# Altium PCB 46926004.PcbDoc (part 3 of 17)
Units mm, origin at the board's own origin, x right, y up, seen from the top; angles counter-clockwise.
Board outline 250 x 200 mm, 6 copper layers (Top Layer, INT1_GND, INT2_SIG, INT3_SIG, INT4_GND, Bottom Layer), stack 1.71 mm thick; 1450 components, 1293 nets, 5656 pads, 2307 vias.
Unrouted connection lines stored in the file: 2.
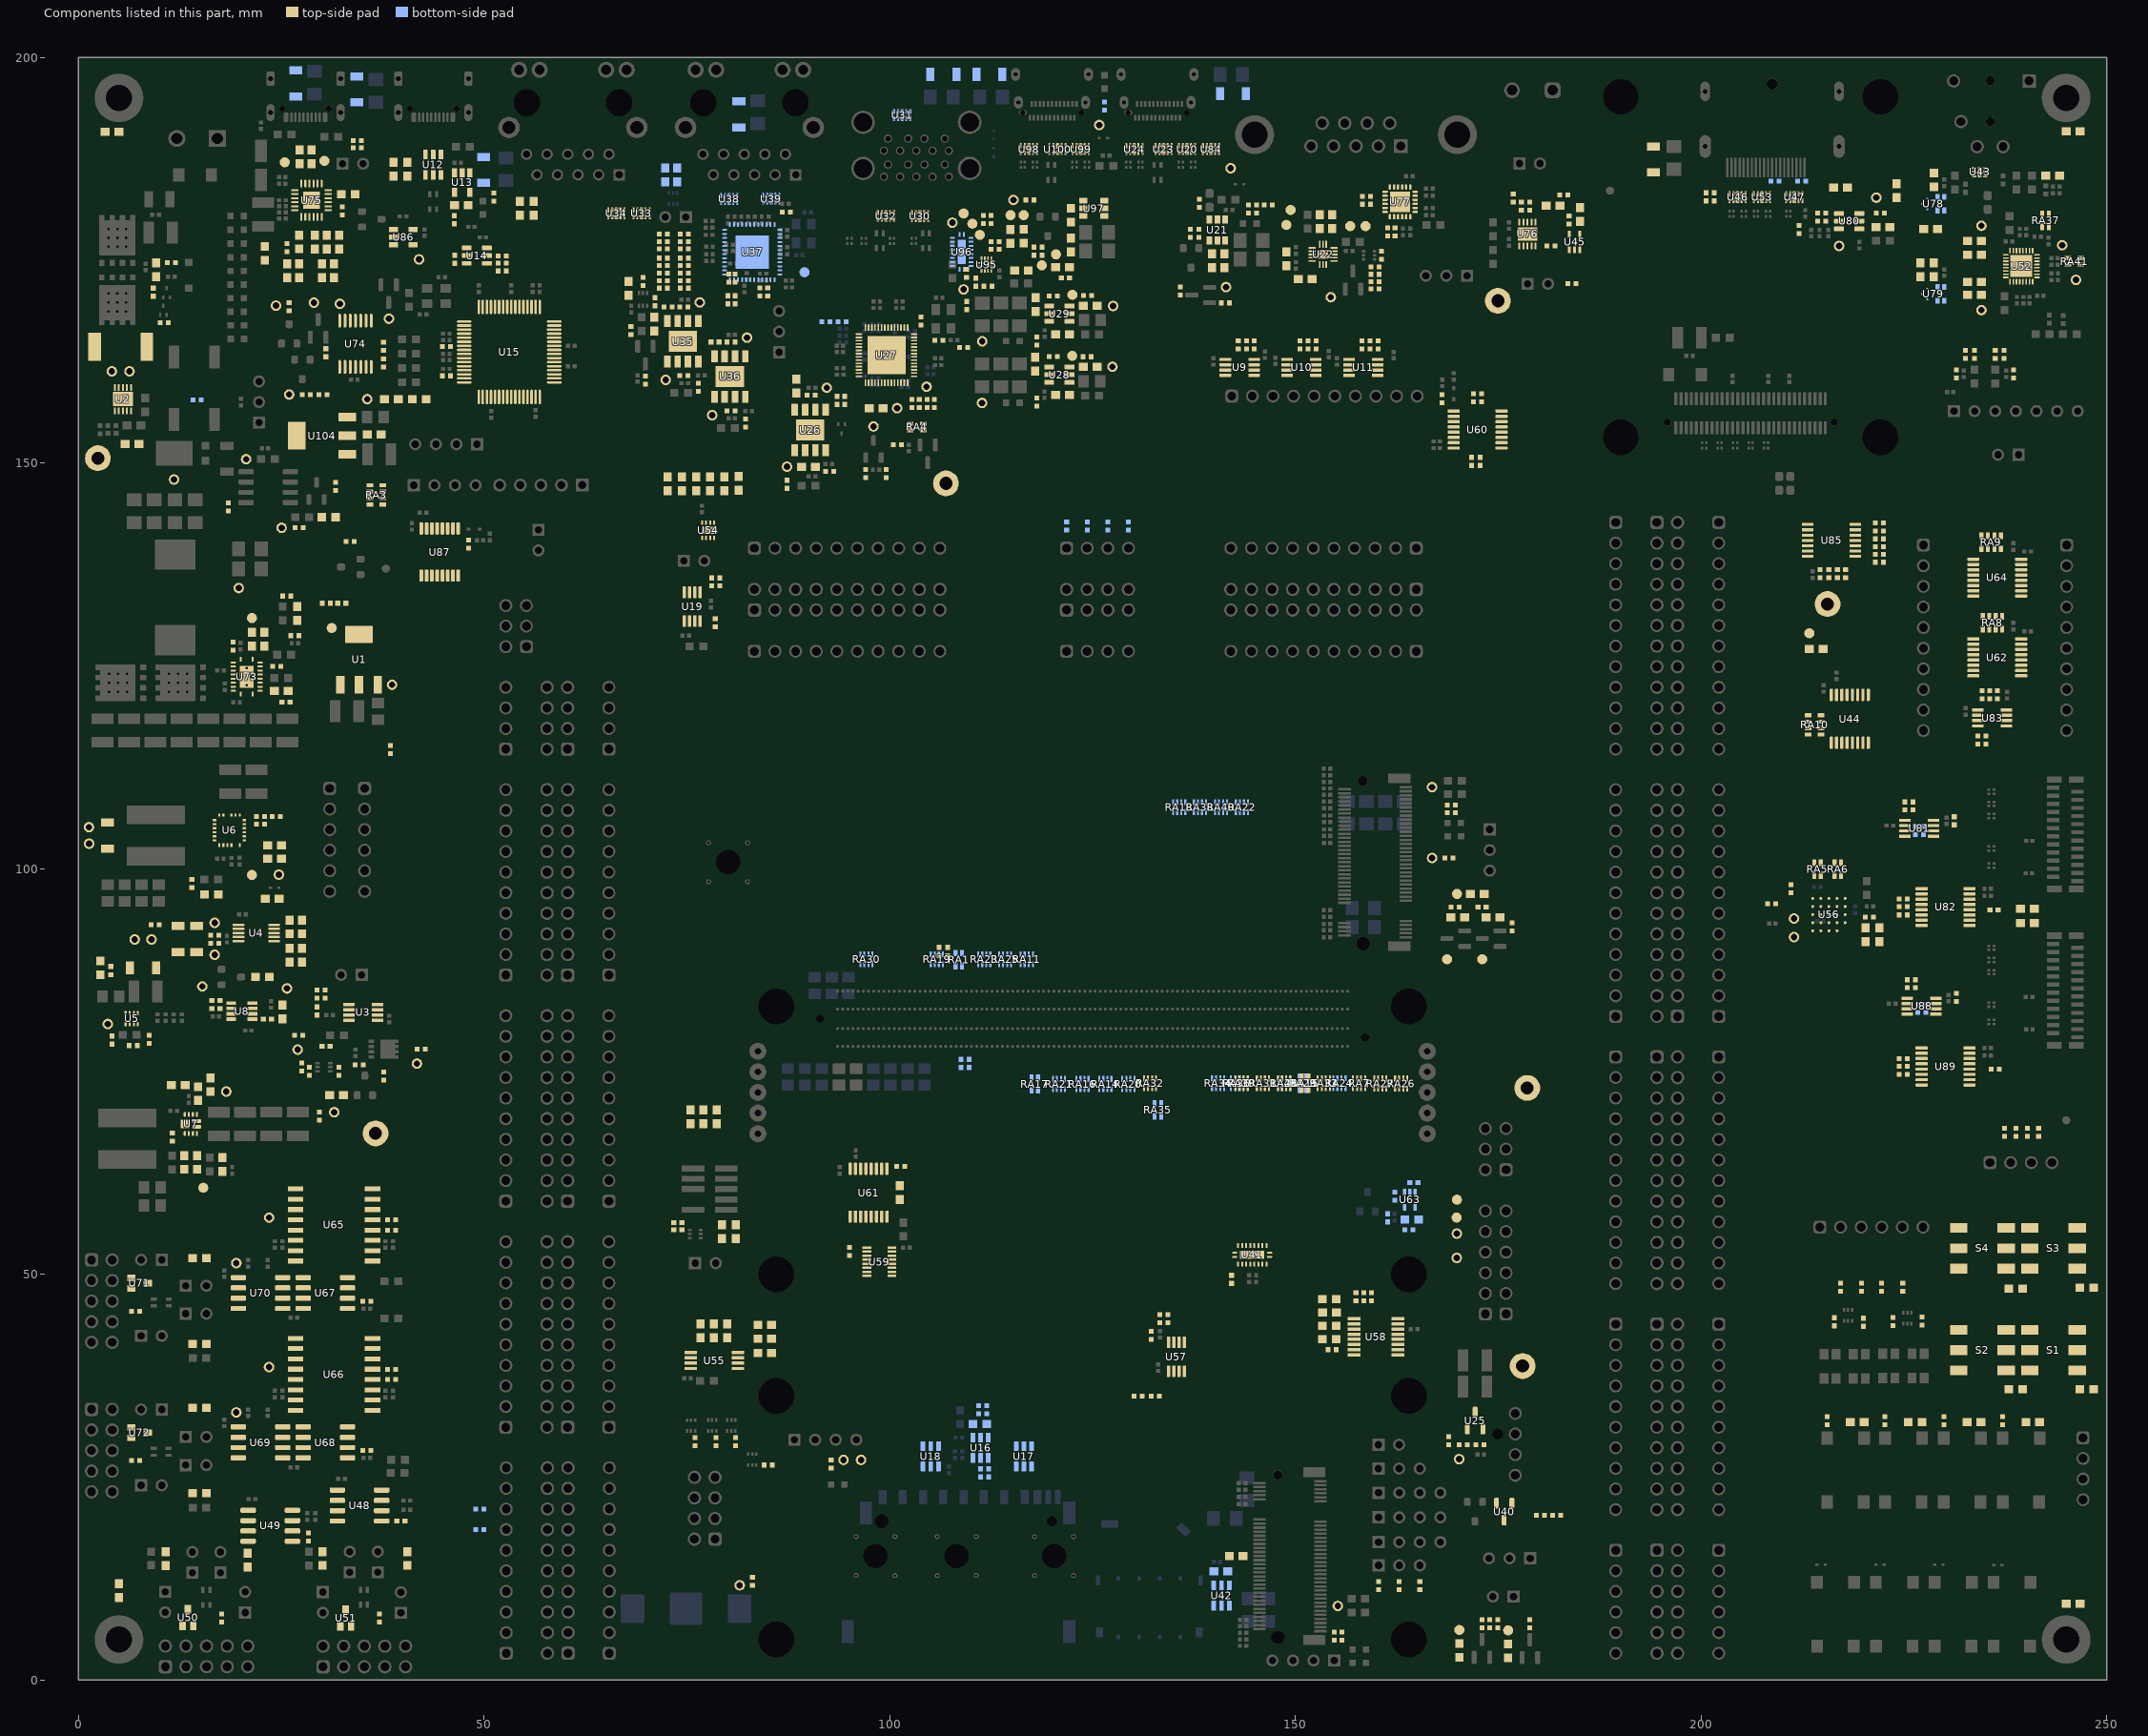
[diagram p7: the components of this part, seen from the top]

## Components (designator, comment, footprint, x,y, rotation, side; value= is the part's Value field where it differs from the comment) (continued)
R6 "1144-Res-0603-24.9K" R/0603 6.623,152.364 r180 top value=24.9K
R7 "1216-Res-0603-20K" R/0603 9.55,173.82 r90 top value=20K
R8 "2225-Res-2512-0.003ohm-2W" R/2512 5.223,164.347 r180 top value=0.003/2W
R9 "1977-Res-0402-100K" R0402_RESC1005L 9.225,171.065 r90 top value=100K
R10 "1572-Res-0402-10K" R0402_RESC1005L 14.645,157.775 r0 bottom value=10K
R11 "0195-Res-0603-0.0ohm" R/0603 245.85,9.425 r0 top value=0.0
R12 "1540-Res-0402-200k" R0402_RESC1005L 29.413,82.465 r270 top value=200K
R13 "2233-Res-0402-4.7K" R0402_RESC1005L 29.925,85.025 r0 top value=4.7K
R14 "2233-Res-0402-4.7K" R0402_RESC1005L 29.925,84.025 r0 top value=4.7K
R15 "0195-Res-0603-0.0ohm" R/0603 27.55,89.325 r90 top value=0.0
R16 "0000-Res-0603-DNP" R/0603 26.05,92.825 r270 top value=DNP
R17 "0195-Res-0603-0.0ohm" R/0603 27.55,92.825 r270 top value=0.0
R18 "0000-Res-0603-DNP" R/0603 26.042,89.325 r90 top value=DNP
R19 "1538-Res-0402-27k" R0402_RESC1005L 37.65,74.42 r90 top value=27K
R20 "1538-Res-0402-27k" R0402_RESC1005L 34.625,75.8 r180 top value=27K
R21 "0257-Res-0402-10ohm" R0402_RESC1005L 16.8,90.825 r180 top value=10
R22 "0034-Res-1206-0.010" R/1206 14.55,91.325 r90 top value=0.010/1W
R23 "0034-Res-1206-0.010" R/1206 12.3,91.325 r90 top value=0.010/1W
R24 "2233-Res-0402-4.7K" R0402_RESC1005L 42.225,77.775 r180 top value=4.7K
R25 "0257-Res-0402-10ohm" R0402_RESC1005L 16.8,91.825 r180 top value=10
R26 "2233-Res-0402-4.7K" R0402_RESC1005L 9.465,93.075 r0 top value=4.7K
R27 "1572-Res-0402-10K" R0402_RESC1005L 4,87.45 r90 top value=10K
R28 "0195-Res-0603-0.0ohm" R/0603 31.8,72.075 r0 top value=0.0
R29 "1538-Res-0402-27k" R0402_RESC1005L 8.725,78.95 r90 top value=27K
R30 "1538-Res-0402-27k" R0402_RESC1005L 6.748,78.2 r0 top value=27K
R31 "1538-Res-0402-27k" R0402_RESC1005L 4.128,78.875 r90 top value=27K
R32 "0195-Res-0603-0.0ohm" R/0603 24.191,102.907 r180 top value=0.0
R33 "0195-Res-0603-0.0ohm" R/0603 16.3,73.375 r270 top value=0.0
R34 "0000-Res-0603-DNP" R/0603 24.195,101.232 r180 top value=DNP
R35 "1977-Res-0402-100K" R0402_RESC1005L 24.4,106.45 r0 top value=100K
R36 "1538-Res-0402-27k" R0402_RESC1005L 22.45,106.45 r0 top value=27K
R37 "1977-Res-0402-100K" R0402_RESC1005L 11.575,66.9 r90 top value=100K
R38 "0195-Res-0603-0.0ohm" R/0603 2.725,87.775 r90 top value=0.0
R39 "0034-Res-1206-0.010" R/1206 7.975,87.775 r180 top value=0.010/1W
R40 "2233-Res-0402-4.7K" R0402_RESC1005L 38.444,114.675 r270 top value=4.7K
R41 "0866-Res-0603-220K" R/0603 14.775,72.275 r90 top value=220K
R42 "0866-Res-0603-220K" R/0603 12.325,73.35 r180 top value=220K
R43 "1572-Res-0402-10K" R0402_RESC1005L 28.351,17.633 r270 top value=10K
R44 "1144-Res-0603-24.9K" R/0603 17.725,63.525 r90 top value=24.9K
R45 "1538-Res-0402-27k" R0402_RESC1005L 13.991,98.175 r90 top value=27K
R46 "1216-Res-0603-20K" R/0603 16.391,96.825 r180 top value=20K
R47 "1550-Res-0402-15K" R0402_RESC1005L 22.45,105.5 r180 top value=15K
R48 "0866-Res-0603-220K" R/0603 14.627,63.8 r90 top value=220K
R49 "1144-Res-0603-24.9K" R/0603 13.052,63.8 r90 top value=24.9K
R50 "1572-Res-0402-10K" R0402_RESC1005L 39.75,19.6 r180 top value=10K
R51 "0034-Res-1206-0.010" R/1206 3.582,104.075 r90 top value=0.010/1W
R52 "1536-Res-0402-1.87K" R0402_RESC1005L 33.504,140.34 r0 top value=1.87K
R53 "1977-Res-0402-100K" R0402_RESC1005L 27.55,75.55 r270 top value=100K
R54 "0195-Res-0603-0.0ohm" R/0603 25.175,82.35 r90 top value=0.0
R55 "1538-Res-0402-27k" R0402_RESC1005L 23.3,81.475 r180 top value=27K
R56 "1977-Res-0402-100K" R0402_RESC1005L 32.125,75.05 r270 top value=100K
R57 "1977-Res-0402-100K" R0402_RESC1005L 28.472,75.05 r270 top value=100K
R58 "1572-Res-0402-10K" R0402_RESC1005L 16.95,82.775 r180 top value=10K
R59 "1572-Res-0402-10K" R0402_RESC1005L 16.95,83.775 r0 top value=10K
R60 "2233-Res-0402-4.7K" R0402_RESC1005L 30.525,78.125 r180 top value=4.7K
R61 "0176-Res-0603-300K" R/0603 70.95,167.11 r90 top value=300K
R62 "0000-Res-0402-DNP" R0402_RESC1005L 72.095,172.487 r180 top value=DNP
R63 "1977-Res-0402-100K" R0402_RESC1005L 71.051,169.889 r270 top value=100K
R64 "0195-Res-0603-0.0ohm" R/0603 22.675,86.65 r0 top value=0.0
R65 "0000-Res-0402-DNP" R0402_RESC1005L 94.122,167.443 r180 bottom value=DNP
R66 "0000-Res-0402-DNP" R0402_RESC1005L 108.8,76 r90 bottom value=DNP
R67 "1572-Res-0402-10K" R0402_RESC1005L 35.55,46.7 r0 top value=10K
R68 "1572-Res-0402-10K" R0402_RESC1005L 35.55,28.275 r0 top value=10K
R69 "1540-Res-0402-200k" R0402_RESC1005L 144.94,164.559 r270 top value=200K
R70 "1540-Res-0402-200k" R0402_RESC1005L 152.56,164.559 r270 top value=200K
R71 "2233-Res-0402-4.7K" R0402_RESC1005L 142.95,164.559 r270 top value=4.7K
R72 "2233-Res-0402-4.7K" R0402_RESC1005L 150.57,164.559 r270 top value=4.7K
R73 "2233-Res-0402-4.7K" R0402_RESC1005L 143.955,164.559 r270 top value=4.7K
R74 "2233-Res-0402-4.7K" R0402_RESC1005L 151.575,164.559 r270 top value=4.7K
R75 "1536-Res-0402-1.87K" R0402_RESC1005L 49.455,18.54 r0 bottom value=1.87K
R76 "1536-Res-0402-1.87K" R0402_RESC1005L 49.455,21.08 r0 bottom value=1.87K
R77 "1540-Res-0402-200k" R0402_RESC1005L 160.18,164.559 r270 top value=200K
R78 "2233-Res-0402-4.7K" R0402_RESC1005L 158.19,164.559 r270 top value=4.7K
R79 "2233-Res-0402-4.7K" R0402_RESC1005L 159.195,164.559 r270 top value=4.7K
R80 "0227-Res-0603-5.1K" R/0603 38.813,186.22 r270 top value=5.1K
R81 "0227-Res-0603-5.1K" R/0603 40.55,186.225 r270 top value=5.1K
R82 "1860-Res-1206-1M-5%-0.25W" R/1206 34.3,196.06 r90 bottom value=1M/0.25W
R83 "2233-Res-0402-4.7K" R0402_RESC1005L 51.2,182.783 r90 top value=4.7K
R84 "0176-Res-0603-300K" R/0603 47.187,181.783 r180 top value=300K
R85 "1539-Res-0402-86.6k" R0402_RESC1005L 46.341,179.994 r90 top value=86.6K
R86 "1538-Res-0402-27k" R0402_RESC1005L 52.24,175.55 r180 top value=27K
R87 "1538-Res-0402-27k" R0402_RESC1005L 52.24,174.625 r180 top value=27K
R88 "1536-Res-0402-1.87K" R0402_RESC1005L 46.39,175.112 r90 top value=1.87K
R89 "1538-Res-0402-27k" R0402_RESC1005L 52.24,173.675 r180 top value=27K
R90 "1538-Res-0402-27k" R0402_RESC1005L 45.34,160.75 r0 top value=27K
R91 "1537-Res-0402-12K" R0402_RESC1005L 45.34,164.35 r0 top value=12K
R92 "1542-Res-0402-1M" R0402_RESC1005L 80.975,29.384 r90 top value=1M
R93 "1542-Res-0402-1M" R0402_RESC1005L 76.009,29.365 r90 top value=1M
R94 "1542-Res-0402-1M" R0402_RESC1005L 78.595,29.384 r90 top value=1M
R95 "1572-Res-0402-10K" R0402_RESC1005L 48.1,140 r270 top value=10K
R96 "0000-Res-0603-DNP" R/0603 111.1,31.58 r0 bottom value=DNP
R97 "1539-Res-0402-86.6k" R0402_RESC1005L 111.694,26.035 r180 bottom value=86.6K
R98 "1539-Res-0402-86.6k" R0402_RESC1005L 111.694,25.035 r180 bottom value=86.6K
R99 "1536-Res-0402-1.87K" R0402_RESC1005L 92.775,26.631 r90 top value=1.87K
R100 "1540-Res-0402-200k" R0402_RESC1005L 78.501,130.298 r90 top value=200K
R101 "1758-Res-0603-2K" R/0603 141.27,174.936 r270 top value=2K
R102 "2233-Res-0402-4.7K" R0402_RESC1005L 78.575,134.885 r180 top value=4.7K
R103 "2233-Res-0402-4.7K" R0402_RESC1005L 78.575,135.835 r180 top value=4.7K
R104 "1538-Res-0402-27k" R0402_RESC1005L 141.37,169.742 r0 top value=27K
R105 "1552-Res-0402-120" R0402_RESC1005L 135.815,171.203 r90 top value=120
R106 "0000-Res-0603-DNP" R/0603 148.871,175.165 r270 top value=DNP
R107 "0000-Res-0603-DNP" R/0603 151.196,172.665 r0 top value=DNP
R108 "1572-Res-0402-10K" R0402_RESC1005L 138.145,182.036 r270 top value=10K
R109 "0000-Res-0603-DNP" R/0603 154.546,179.74 r90 top value=DNP
R110 "0195-Res-0603-0.0ohm" R/0603 152.996,179.74 r90 top value=0.0
R111 "1552-Res-0402-120" R0402_RESC1005L 159.796,174.165 r0 top value=120
R112 "1758-Res-0603-2K" R/0603 139.712,174.936 r270 top value=2K
R113 "1572-Res-0402-10K" R0402_RESC1005L 160.596,175.615 r90 top value=10K
R114 "1538-Res-0402-27k" R0402_RESC1005L 146.64,181.81 r180 top value=27K
R115 "1977-Res-0402-100K" R0402_RESC1005L 201.6,182.817 r270 top value=100K
R116 "1572-Res-0402-10K" R0402_RESC1005L 159.796,173.265 r180 top value=10K
R117 "1572-Res-0402-10K" R0402_RESC1005L 159.796,172.365 r180 top value=10K
R118 "1572-Res-0402-10K" R0402_RESC1005L 159.796,171.465 r180 top value=10K
R119 "2233-Res-0402-4.7K" R0402_RESC1005L 144.695,180.8 r180 top value=4.7K
R120 "1860-Res-1206-1M-5%-0.25W" R/1206 142.3,195.55 r0 bottom value=1M/0.25W
R121 "1552-Res-0402-120" R0402_RESC1005L 69.576,172.39 r90 top value=120
R122 "1572-Res-0402-10K" R0402_RESC1005L 100.945,152.249 r0 top value=10K
R123 "1552-Res-0402-120" R0402_RESC1005L 92.585,148.95 r0 top value=120
R124 "0000-Res-0603-DNP" R/0603 89.976,149.549 r180 top value=DNP
R125 "0000-Res-0402-DNP" R0402_RESC1005L 102.737,157.337 r270 top value=DNP
R126 "1540-Res-0402-200k" R0402_RESC1005L 103.646,157.337 r90 top value=200K
R127 "1540-Res-0402-200k" R0402_RESC1005L 105.495,157.337 r90 top value=200K
R128 "0000-Res-0402-DNP" R0402_RESC1005L 104.596,157.337 r270 top value=DNP
R129 "1538-Res-0402-27k" R0402_RESC1005L 90.326,158.381 r0 top value=27K
R130 "0342-Res-0603-56K" R/0603 88.481,159.504 r90 top value=56K
R131 "0195-Res-0603-0.0ohm" R/0603 98.316,156.764 r0 top value=0.0
R132 "1537-Res-0402-12K" R0402_RESC1005L 103.872,167.496 r270 top value=12K
R133 "1650-Res-0402-1K" R0402_RESC1005L 109.102,164.225 r180 top value=1K
R134 "1538-Res-0402-27k" R0402_RESC1005L 93.52,157.73 r90 top value=27K
R135 "1572-Res-0402-10K" R0402_RESC1005L 99.558,148.698 r90 top value=10K
R136 "1572-Res-0402-10K" R0402_RESC1005L 94.47,157.73 r90 top value=10K
R137 "1572-Res-0402-10K" R0402_RESC1005L 97.046,148.698 r90 top value=10K
R138 "0000-Res-0603-DNP" R/0603 121.304,158.4 r0 top value=DNP
R139 "0000-Res-0603-DNP" R/0603 121.311,165.863 r0 top value=DNP
R140 "0000-Res-0402-DNP" R0402_RESC1005L 120.154,163.14 r180 top value=DNP
R141 "0000-Res-0402-DNP" R0402_RESC1005L 120.144,170.613 r180 top value=DNP
R142 "1144-Res-0603-24.9K" R/0603 117.898,162.19 r270 top value=24.9K
R143 "1144-Res-0603-24.9K" R/0603 117.975,169.553 r270 top value=24.9K
R144 "2233-Res-0402-4.7K" R0402_RESC1005L 118.129,157.53 r90 top value=4.7K
R145 "2233-Res-0402-4.7K" R0402_RESC1005L 118.129,165.059 r90 top value=4.7K
R146 "0043-Res-0603-510ohm" R/0603 56.105,181.405 r90 top value=510
R147 "0043-Res-0603-510ohm" R/0603 54.4,181.407 r90 top value=510
R148 "1860-Res-1206-1M-5%-0.25W" R/1206 49.95,186.12 r270 bottom value=1M/0.25W
R149 "0000-Res-0402-DNP" R0402_RESC1005L 74.67,172.487 r180 top value=DNP
R150 "0000-Res-0402-DNP" R0402_RESC1005L 72.095,171.562 r180 top value=DNP
R151 "0000-Res-0402-DNP" R0402_RESC1005L 74.67,171.562 r180 top value=DNP
R152 "1572-Res-0402-10K" R0402_RESC1005L 80.92,172.78 r90 top value=10K
R153 "2313-Res-0402-2.49K" R0402_RESC1005L 80.95,170.125 r90 top value=2.49K
R154 "1572-Res-0402-10K" R0402_RESC1005L 80.15,172.775 r90 top value=10K
R155 "2313-Res-0402-2.49K" R0402_RESC1005L 80.075,170.125 r90 top value=2.49K
R156 "2077-Res-0402-5.76K" R0402_RESC1005L 72.095,173.412 r0 top value=5.76k
R157 "2313-Res-0402-2.49K" R0402_RESC1005L 74.67,173.412 r180 top value=2.49K
R158 "0000-Res-0402-DNP" R0402_RESC1005L 72.095,176.387 r180 top value=DNP
R159 "1552-Res-0402-120" R0402_RESC1005L 76.395,159.348 r270 top value=120
R160 "1552-Res-0402-120" R0402_RESC1005L 82.207,154.95 r270 top value=120
R161 "0000-Res-0402-DNP" R0402_RESC1005L 74.67,176.387 r180 top value=DNP
R162 "1572-Res-0402-10K" R0402_RESC1005L 72.095,178.237 r180 top value=10K
R163 "2313-Res-0402-2.49K" R0402_RESC1005L 74.67,178.237 r180 top value=2.49K
R164 "0000-Res-0402-DNP" R0402_RESC1005L 72.095,177.312 r180 top value=DNP
R165 "1538-Res-0402-27k" R0402_RESC1005L 74.62,160.78 r180 top value=27K
R166 "1538-Res-0402-27k" R0402_RESC1005L 80.425,156.442 r180 top value=27K
R167 "0000-Res-0402-DNP" R0402_RESC1005L 74.67,177.312 r180 top value=DNP
R168 "0000-Res-0402-DNP" R0402_RESC1005L 72.095,175.262 r180 top value=DNP
R169 "1572-Res-0402-10K" R0402_RESC1005L 74.625,169.254 r0 top value=10K
R170 "2313-Res-0402-2.49K" R0402_RESC1005L 80.43,164.925 r0 top value=2.49K
R171 "1572-Res-0402-10K" R0402_RESC1005L 78.472,164.925 r0 top value=10K
R172 "2233-Res-0402-4.7K" R0402_RESC1005L 72.68,169.254 r0 top value=4.7K
R173 "1572-Res-0402-10K" R0402_RESC1005L 68.098,166.31 r90 top value=10K
R174 "2233-Res-0402-4.7K" R0402_RESC1005L 84.958,171.083 r90 top value=4.7K
R175 "1536-Res-0402-1.87K" R0402_RESC1005L 83.988,171.075 r90 top value=1.87K
R176 "2527-Res-0402-11K" R0402_RESC1005L 87.251,180.95 r180 top value=11K
R177 "0043-Res-0603-510ohm" R/0603 73.821,185.512 r90 bottom value=510
R178 "0043-Res-0603-510ohm" R/0603 72.345,185.512 r90 bottom value=510
R179 "1860-Res-1206-1M-5%-0.25W" R/1206 81.4,192.965 r270 bottom value=1M/0.25W
R180 "0000-Res-0603-DNP" R/0603 67.8,171.55 r270 top value=DNP
R181 "1572-Res-0402-10K" R0402_RESC1005L 162.231,59.648 r270 bottom value=10K
R182 "1538-Res-0402-27k" R0402_RESC1005L 173.937,6.923 r270 top value=27K
R183 "0195-Res-0603-0.0ohm" R/0603 214.2,127.1 r180 top value=0.0
R184 "0000-Res-0402-DNP" R0402_RESC1005L 172.987,6.923 r270 top value=DNP
R185 "0195-Res-0603-0.0ohm" R/0603 142.708,15.275 r180 top value=0.0
R186 "1572-Res-0402-10K" R0402_RESC1005L 161.364,56.959 r90 bottom value=10K
R187 "1536-Res-0402-1.87K" R0402_RESC1005L 155.708,5.405 r90 top value=1.87K
R188 "1572-Res-0402-10K" R0402_RESC1005L 164.6,61.321 r0 bottom value=10K
R189 "1572-Res-0402-10K" R0402_RESC1005L 168.083,157.91 r270 top value=10K
R190 "1539-Res-0402-86.6k" R0402_RESC1005L 163.985,55.471 r180 bottom value=86.6K
R191 "0000-Res-0603-DNP" R/0603 140.791,13.375 r0 bottom value=DNP
R192 "0195-Res-0603-0.0ohm" R/0603 233.7,175.675 r180 top value=0.0
R193 "1538-Res-0402-27k" R0402_RESC1005L 165.33,11.625 r90 top value=27K
R194 "0195-Res-0603-0.0ohm" R/0603 164.335,56.758 r0 bottom value=0.0
R195 "1538-Res-0402-27k" R0402_RESC1005L 162.79,11.625 r90 top value=27K
R196 "1536-Res-0402-1.87K" R0402_RESC1005L 160.25,11.625 r270 top value=1.87K
R197 "1536-Res-0402-1.87K" R0402_RESC1005L 154.78,5.405 r90 top value=1.87K
R198 "1538-Res-0402-27k" R0402_RESC1005L 176.693,92.85 r270 top value=27K
R199 "0195-Res-0603-0.0ohm" R/0603 172.396,96.9 r180 top value=0.0
R200 "0000-Res-0402-DNP" R0402_RESC1005L 172.996,95.27 r180 top value=DNP
R202 "1536-Res-0402-1.87K" R0402_RESC1005L 169.194,107.862 r180 top value=1.87K
R203 "1538-Res-0402-27k" R0402_RESC1005L 168.925,101.321 r0 top value=27K
R204 "1536-Res-0402-1.87K" R0402_RESC1005L 169.2,106.9 r180 top value=1.87K
R205 "2199-Res-0603-60.4" R/0603 10.736,14.959 r90 top value=60.4
R206 "2199-Res-0603-60.4" R/0603 30.075,14.975 r90 top value=60.4
R207 "2199-Res-0603-60.4" R/0603 20.876,14.783 r90 top value=60.4
R208 "2199-Res-0603-60.4" R/0603 40.525,14.975 r90 top value=60.4
R210 "1552-Res-0402-120" R0402_RESC1005L 111.45,32.835 r180 bottom value=120
R212 "0195-Res-0603-0.0ohm" R/0603 233.675,177.375 r180 top value=0.0
R213 "1552-Res-0402-120" R0402_RESC1005L 87.32,147.386 r270 top value=120
R214 "0195-Res-0603-0.0ohm" R/0603 233.7,170.75 r180 top value=0.0
R215 "1572-Res-0402-10K" R0402_RESC1005L 231.45,161 r90 top value=10K
R216 "0045-Res-0603-2.2K" R/0603 243.325,185.45 r0 top value=2.2K
R217 "0195-Res-0603-0.0ohm" R/0603 224.075,183.575 r90 top value=0.0
R218 "1572-Res-0402-10K" R0402_RESC1005L 222.1,180.792 r0 top value=10K
R219 "0000-Res-0402-DNP" R0402_RESC1005L 74.67,175.262 r180 top value=DNP
R220 "1552-Res-0402-120" R0402_RESC1005L 124.322,163.104 r0 top value=120
R221 "0195-Res-0603-0.0ohm" R/0603 72.62,147.46 r270 top value=0.0
R222 "0195-Res-0603-0.0ohm" R/0603 77.87,147.46 r270 top value=0.0
R223 "0195-Res-0603-0.0ohm" R/0603 79.62,147.46 r270 top value=0.0
R224 "0000-Res-0603-DNP" R/0603 74.37,147.46 r270 top value=DNP
R225 "0000-Res-0603-DNP" R/0603 76.12,147.46 r270 top value=DNP
R226 "0000-Res-0603-DNP" R/0603 81.37,147.51 r270 top value=DNP
R227 "1536-Res-0402-1.87K" R0402_RESC1005L 83.085,12.176 r90 top value=1.87K
R228 "0195-Res-0603-0.0ohm" R/0603 220.25,91.875 r270 top value=0.0
R229 "0000-Res-0603-DNP" R/0603 222,91.875 r270 top value=DNP
R230 "1572-Res-0402-10K" R0402_RESC1005L 220.75,94.05 r180 top value=10K
R231 "1572-Res-0402-10K" R0402_RESC1005L 208.685,95.7 r0 top value=10K
R232 "0195-Res-0603-0.0ohm" R/0603 76.7,43.05 r270 top value=0.0
R233 "0195-Res-0603-0.0ohm" R/0603 78.3,43.05 r270 top value=0.0
R234 "0195-Res-0603-0.0ohm" R/0603 79.95,43.05 r270 top value=0.0
R235 "0000-Res-0603-DNP" R/0603 84.6,40.3 r180 top value=DNP
R236 "0000-Res-0603-DNP" R/0603 84.6,42.05 r180 top value=DNP
R237 "0000-Res-0603-DNP" R/0603 84.6,43.8 r180 top value=DNP
R238 "1572-Res-0402-10K" R0402_RESC1005L 211.06,97.54 r270 top value=10K
R239 "2233-Res-0402-4.7K" R0402_RESC1005L 30.536,132.722 r180 top value=4.7K
R240 "0043-Res-0603-510ohm" R/0603 240.884,31.811 r0 top value=510
R241 "1539-Res-0402-86.6k" R0402_RESC1005L 237.162,31.964 r270 top value=86.6K
R242 "0043-Res-0603-510ohm" R/0603 233.634,31.811 r0 top value=510
R243 "1539-Res-0402-86.6k" R0402_RESC1005L 229.912,31.964 r270 top value=86.6K
R244 "0043-Res-0603-510ohm" R/0603 226.384,31.811 r0 top value=510
R245 "1539-Res-0402-86.6k" R0402_RESC1005L 222.662,31.964 r270 top value=86.6K
R246 "0043-Res-0603-510ohm" R/0603 219.259,31.811 r0 top value=510
R247 "1539-Res-0402-86.6k" R0402_RESC1005L 215.537,31.964 r270 top value=86.6K
R248 "1540-Res-0402-200k" R0402_RESC1005L 132.236,42.483 r90 top value=200K
R249 "2233-Res-0402-4.7K" R0402_RESC1005L 133.802,45.05 r0 top value=4.7K
R250 "2233-Res-0402-4.7K" R0402_RESC1005L 133.802,44.05 r0 top value=4.7K
R251 "0195-Res-0603-0.0ohm" R/0603 154.174,46.933 r0 top value=0.0
R252 "0195-Res-0603-0.0ohm" R/0603 154.174,43.633 r0 top value=0.0
R253 "0000-Res-0603-DNP" R/0603 154.189,45.283 r0 top value=DNP
R254 "0000-Res-0603-DNP" R/0603 154.174,41.983 r0 top value=DNP
R255 "0043-Res-0603-510ohm" R/0603 238.775,35.825 r180 top value=510
R256 "1977-Res-0402-100K" R0402_RESC1005L 200.625,182.817 r270 top value=100K
R257 "1977-Res-0402-100K" R0402_RESC1005L 240.2,67.5 r270 top value=100K
R258 "0043-Res-0603-510ohm" R/0603 238.775,48.225 r180 top value=510
R259 "1977-Res-0402-100K" R0402_RESC1005L 237.4,67.5 r270 top value=100K
R260 "0043-Res-0603-510ohm" R/0603 247.525,35.825 r180 top value=510
R261 "1977-Res-0402-100K" R0402_RESC1005L 241.6,67.5 r270 top value=100K
R262 "0043-Res-0603-510ohm" R/0603 247.525,48.375 r180 top value=510
R263 "1977-Res-0402-100K" R0402_RESC1005L 238.8,67.5 r270 top value=100K
R264 "1536-Res-0402-1.87K" R0402_RESC1005L 180.194,20.306 r180 top value=1.87K
R265 "1536-Res-0402-1.87K" R0402_RESC1005L 182.189,20.306 r0 top value=1.87K
R266 "1572-Res-0402-10K" R0402_RESC1005L 154.524,40.712 r0 top value=10K
R267 "1860-Res-1206-1M-5%-0.25W" R/1206 194.125,187.417 r270 top value=1M/0.25W
R268 "1572-Res-0402-10K" R0402_RESC1005L 159.359,47.243 r270 top value=10K
R269 "1572-Res-0402-10K" R0402_RESC1005L 158.411,47.243 r270 top value=10K
R270 "1977-Res-0402-100K" R0402_RESC1005L 212.05,178.767 r270 top value=100K
R271 "1572-Res-0402-10K" R0402_RESC1005L 157.461,47.243 r270 top value=10K
R272 "2233-Res-0402-4.7K" R0402_RESC1005L 168.875,29.5 r90 top value=4.7K
R273 "1572-Res-0402-10K" R0402_RESC1005L 170.7,29 r0 top value=10K
R274 "1572-Res-0402-10K" R0402_RESC1005L 172.737,29 r0 top value=10K
R275 "1539-Res-0402-86.6k" R0402_RESC1005L 224.85,48.4 r90 top value=86.6K
R276 "1539-Res-0402-86.6k" R0402_RESC1005L 222.25,48.4 r90 top value=86.6K
R277 "1539-Res-0402-86.6k" R0402_RESC1005L 219.75,48.4 r90 top value=86.6K
R278 "1539-Res-0402-86.6k" R0402_RESC1005L 217.2,48.4 r90 top value=86.6K
R279 "1572-Res-0402-10K" R0402_RESC1005L 227.225,44.25 r90 top value=10K
R280 "1572-Res-0402-10K" R0402_RESC1005L 223.625,44.2 r90 top value=10K
R281 "1572-Res-0402-10K" R0402_RESC1005L 220.025,44.1 r90 top value=10K
R282 "1572-Res-0402-10K" R0402_RESC1005L 216.425,44.15 r90 top value=10K
R283 "1538-Res-0402-27k" R0402_RESC1005L 95.015,52.8 r90 top value=27K
R284 "0000-Res-0603-DNP" R/0603 101.239,60.089 r270 top value=DNP
R285 "1538-Res-0402-27k" R0402_RESC1005L 101.364,63.314 r180 top value=27K
R286 "0000-Res-0603-DNP" R/0603 77.03,69.4 r90 top value=DNP
R287 "0195-Res-0603-0.0ohm" R/0603 78.65,69.4 r90 top value=0.0
R288 "0000-Res-0603-DNP" R/0603 75.425,69.4 r90 top value=DNP
R289 "1977-Res-0402-100K" R0402_RESC1005L 38.6,56.725 r0 top value=100K
R290 "1977-Res-0402-100K" R0402_RESC1005L 38.6,38.3 r0 top value=100K
R291 "1650-Res-0402-1K" R0402_RESC1005L 38.6,55.425 r180 top value=1K
R292 "1650-Res-0402-1K" R0402_RESC1005L 38.6,37.025 r180 top value=1K
R293 "2199-Res-0603-60.4" R/0603 14.925,41.442 r0 top value=60.4
R294 "2199-Res-0603-60.4" R/0603 14.925,52.025 r0 top value=60.4
R295 "2199-Res-0603-60.4" R/0603 14.925,23.025 r0 top value=60.4
R296 "2199-Res-0603-60.4" R/0603 14.925,33.55 r0 top value=60.4
R297 "0195-Res-0603-0.0ohm" R/0603 233.7,172.325 r180 top value=0.0
R298 "1552-Res-0402-120" R0402_RESC1005L 124.361,170.646 r0 top value=120
R299 "0195-Res-0603-0.0ohm" R/0603 228.275,178.825 r0 top value=0.0
R300 "0195-Res-0603-0.0ohm" R/0603 228.7,184.9 r270 top value=0.0
R301 "0195-Res-0603-0.0ohm" R/0603 176.225,3.59 r90 top value=0.0
R302 "0195-Res-0603-0.0ohm" R/0603 227.05,173.825 r270 top value=0.0
R303 "1216-Res-0603-20K" R/0603 23.875,96.325 r0 top value=20K
R304 "1216-Res-0603-20K" R/0603 24.992,121.925 r180 top value=20K
R305 "1016-Res-0402-240ohm" R0402_RESC1005L 19.08,127.425 r90 top value=240
R306 "1537-Res-0402-12K" R0402_RESC1005L 26.692,128.725 r0 top value=12K
R307 "1977-Res-0402-100K" R0402_RESC1005L 25.592,120.525 r180 top value=100K
R308 "0195-Res-0603-0.0ohm" R/0603 170.2,3.64 r90 top value=0.0
R309 "1144-Res-0603-24.9K" R/0603 26.992,131.475 r270 top value=24.9K
R310 "1216-Res-0603-20K" R/0603 22.892,128.275 r270 top value=20K
R311 "1216-Res-0603-20K" R/0603 21.392,128.275 r270 top value=20K
R312 "2233-Res-0402-4.7K" R0402_RESC1005L 24.442,124.925 r0 top value=4.7K
R313 "1572-Res-0402-10K" R0402_RESC1005L 28.1,158.45 r0 top value=10K
R314 "1572-Res-0402-10K" R0402_RESC1005L 30.5,163.6 r270 top value=10K
R315 "0227-Res-0603-5.1K" R/0603 22.995,175.853 r90 top value=5.1K
R316 "1650-Res-0402-1K" R0402_RESC1005L 25.975,169.275 r270 top value=1K
R317 "1977-Res-0402-100K" R0402_RESC1005L 32.5,181.1 r90 top value=100K
R318 "1807-Res-0402-330Ohm" R0402_RESC1005L 25.695,133.605 r180 top value=330
R319 "1860-Res-1206-1M-5%-0.25W" R/1206 26.775,196.785 r270 bottom value=1M/0.25W
R320 "0000-Res-0603-DNP" R/0603 27.25,187.75 r90 top value=DNP
R321 "0000-Res-0603-DNP" R/0603 28.75,187.75 r90 top value=DNP
R322 "0000-Res-0402-DNP" R0402_RESC1005L 178.9,6.928 r270 top value=DNP
R323 "1216-Res-0603-20K" R/0603 42.015,157.868 r0 top value=20K
R324 "1550-Res-0402-15K" R0402_RESC1005L 37.6,164.4 r90 top value=15K
R325 "0176-Res-0603-300K" R/0603 36.45,153.541 r0 top value=300K
R326 "1216-Res-0603-20K" R/0603 38.575,157.873 r0 top value=20K
R327 "1572-Res-0402-10K" R0402_RESC1005L 37.6,162.35 r270 top value=10K
R328 "0000-Res-0603-DNP" R/0603 31.5,173.699 r270 top value=DNP
R329 "0195-Res-0603-0.0ohm" R/0603 30,173.7 r90 top value=0.0
R330 "0000-Res-0603-DNP" R/0603 30.625,177.225 r270 top value=DNP
R331 "0195-Res-0603-0.0ohm" R/0603 32.125,177.224 r90 top value=0.0
R332 "1572-Res-0402-10K" R0402_RESC1005L 27.21,142.03 r180 top value=10K
R333 "1572-Res-0402-10K" R0402_RESC1005L 30.125,158.45 r0 top value=10K
R334 "1572-Res-0402-10K" R0402_RESC1005L 25.725,176.553 r270 top value=10K
R335 "1538-Res-0402-27k" R0402_RESC1005L 31.7,147.125 r90 top value=27K
R336 "1216-Res-0603-20K" R/0603 30.85,143.33 r0 top value=20K
R337 "0195-Res-0603-0.0ohm" R/0603 27.225,173.703 r270 top value=0.0
R338 "0000-Res-0603-DNP" R/0603 27.225,177.253 r270 top value=DNP
R339 "0195-Res-0603-0.0ohm" R/0603 33.25,183.15 r180 top value=0.0
R340 "0195-Res-0603-0.0ohm" R/0603 228.675,173.825 r270 top value=0.0
R341 "0195-Res-0603-0.0ohm" R/0603 170.021,93.985 r180 top value=0.0
R342 "0000-Res-0603-DNP" R/0603 29.125,177.225 r270 top value=DNP
R343 "1572-Res-0402-10K" R0402_RESC1005L 183.725,179.975 r270 top value=10K
R344 "1977-Res-0402-100K" R0402_RESC1005L 184.075,172.1 r180 top value=100K
R345 "1572-Res-0402-10K" R0402_RESC1005L 183.1,183.035 r180 top value=10K
R346 "0000-Res-0603-DNP" R/0603 181.75,181.71 r180 top value=DNP
R347 "1807-Res-0402-330Ohm" R0402_RESC1005L 10.575,167.28 r0 top value=330
R348 "0257-Res-0402-10ohm" R0402_RESC1005L 178.875,181.65 r270 top value=10
R349 "0257-Res-0402-10ohm" R0402_RESC1005L 177.855,181.65 r270 top value=10
R350 "1552-Res-0402-120" R0402_RESC1005L 176.855,182.65 r270 top value=120
R351 "1650-Res-0402-1K" R0402_RESC1005L 11.45,174.72 r180 top value=1K
R352 "1572-Res-0402-10K" R0402_RESC1005L 92.149,167.443 r180 bottom value=10K
R353 "0257-Res-0402-10ohm" R0402_RESC1005L 106.061,165.138 r0 top value=10
R354 "0195-Res-0603-0.0ohm" R/0603 124.711,169.363 r180 top value=0.0
R355 "0195-Res-0603-0.0ohm" R/0603 124.691,161.872 r180 top value=0.0
R356 "1552-Res-0402-120" R0402_RESC1005L 37.1,7.625 r90 top value=120
R357 "1552-Res-0402-120" R0402_RESC1005L 17.661,7.638 r90 top value=120
R358 "1572-Res-0402-10K" R0402_RESC1005L 32.461,132.722 r0 top value=10K
R359 "0195-Res-0603-0.0ohm" R/0603 240.225,95.05 r180 top value=0.0
R360 "1977-Res-0402-100K" R0402_RESC1005L 224.93,96.25 r0 top value=100K
R361 "1977-Res-0402-100K" R0402_RESC1005L 224.93,95.319 r0 top value=100K
R362 "1977-Res-0402-100K" R0402_RESC1005L 224.93,94.3 r0 top value=100K
R363 "1540-Res-0402-200k" R0402_RESC1005L 231.2,105.9 r270 top value=200K
R364 "2233-Res-0402-4.7K" R0402_RESC1005L 225.62,108.23 r0 top value=4.7K
R365 "2233-Res-0402-4.7K" R0402_RESC1005L 225.62,107.24 r0 top value=4.7K
R366 "1977-Res-0402-100K" R0402_RESC1005L 236.098,94.92 r180 top value=100K
R367 "0195-Res-0603-0.0ohm" R/0603 240.225,93.275 r180 top value=0.0
R368 "1977-Res-0402-100K" R0402_RESC1005L 224.923,76.598 r0 top value=100K
R369 "1977-Res-0402-100K" R0402_RESC1005L 224.923,75.623 r0 top value=100K
R370 "1977-Res-0402-100K" R0402_RESC1005L 224.923,74.651 r0 top value=100K
R371 "1540-Res-0402-200k" R0402_RESC1005L 231.44,84.145 r270 top value=200K
R372 "2233-Res-0402-4.7K" R0402_RESC1005L 225.904,86.314 r0 top value=4.7K
R373 "2233-Res-0402-4.7K" R0402_RESC1005L 225.904,85.335 r0 top value=4.7K
R374 "1977-Res-0402-100K" R0402_RESC1005L 236.232,75.298 r180 top value=100K
R375 "1977-Res-0402-100K" R0402_RESC1005L 112.495,180.012 r90 top value=100K
R376 "1977-Res-0402-100K" R0402_RESC1005L 111.554,180.01 r90 top value=100K
R377 "1977-Res-0402-100K" R0402_RESC1005L 109.456,173.397 r270 top value=100K
R378 "1538-Res-0402-27k" R0402_RESC1005L 142.121,49.385 r90 top value=27K
R379 "1538-Res-0402-27k" R0402_RESC1005L 109.499,169.414 r90 top value=27K
R380 "1552-Res-0402-120" R0402_RESC1005L 7.05,27.05 r0 top value=120
R381 "1552-Res-0402-120" R0402_RESC1005L 7.057,45.467 r0 top value=120
R382 "1572-Res-0402-10K" R0402_RESC1005L 162.275,178.5 r270 top value=10K
R383 "1572-Res-0402-10K" R0402_RESC1005L 158.75,181.9 r180 top value=10K
R384 "1572-Res-0402-10K" R0402_RESC1005L 158.75,182.85 r180 top value=10K
R385 "1572-Res-0402-10K" R0402_RESC1005L 161.35,178.5 r270 top value=10K
R386 "0000-Res-0603-DNP" R/0603 116.225,173.735 r0 top value=DNP
R387 "2233-Res-0402-4.7K" R0402_RESC1005L 112.995,176.361 r0 top value=4.7K
R388 "0227-Res-0603-5.1K" R/0603 25.725,173.703 r90 top value=5.1K
R389 "1809-Res-0402-887K" R0402_RESC1005L 112.995,177.305 r0 top value=887K
R390 "0000-Res-0603-DNP" R/0603 122.321,176.871 r270 top value=DNP
R391 "1977-Res-0402-100K" R0402_RESC1005L 117.295,182.432 r0 top value=100K
R392 "0000-Res-0402-DNP" R0402_RESC1005L 121.65,172.843 r0 top value=DNP
R393 "1977-Res-0402-100K" R0402_RESC1005L 212.375,184.757 r180 bottom value=100K
R394 "1977-Res-0402-100K" R0402_RESC1005L 110.627,172.293 r90 top value=100K
R395 "1552-Res-0402-120" R0402_RESC1005L 138.08,178.338 r270 top value=120
R396 "2233-Res-0402-4.7K" R0402_RESC1005L 126.482,194 r270 bottom value=4.7K
R397 "1860-Res-1206-1M-5%-0.25W" R/1206 112.29,197.91 r180 bottom value=1M/0.25W
R398 "1860-Res-1206-1M-5%-0.25W" R/1206 106.61,197.91 r0 bottom value=1M/0.25W
R399 "1977-Res-0402-100K" R0402_RESC1005L 209.1,184.757 r0 bottom value=100K
R400 "1552-Res-0402-120" R0402_RESC1005L 69.876,160.224 r270 top value=120
R401 "1552-Res-0402-120" R0402_RESC1005L 112.1,171.8 r180 top value=120
R402 "2233-Res-0402-4.7K" R0402_RESC1005L 34.35,188.85 r180 top value=4.7K
R403 "2233-Res-0402-4.7K" R0402_RESC1005L 34.35,189.75 r180 top value=4.7K
R404 "1977-Res-0402-100K" R0402_RESC1005L 137.03,178.338 r270 top value=100K
R405 "0227-Res-0603-5.1K" R/0603 122.321,180.55 r270 top value=5.1K
R406 "0195-Res-0603-0.0ohm" R/0603 174.371,93.985 r180 top value=0.0
R407 "0000-Res-0603-DNP" R/0603 185.05,180.631 r90 top value=DNP
R408 "1572-Res-0402-10K" R0402_RESC1005L 217.8,136.36 r270 top value=10K
R409 "1536-Res-0402-1.87K" R0402_RESC1005L 226.416,104.725 r90 bottom value=1.87K
R410 "1536-Res-0402-1.87K" R0402_RESC1005L 227.409,104.725 r90 bottom value=1.87K
R411 "1536-Res-0402-1.87K" R0402_RESC1005L 226.7,82.8 r90 bottom value=1.87K
R412 "1536-Res-0402-1.87K" R0402_RESC1005L 227.694,82.8 r90 bottom value=1.87K
R413 "1536-Res-0402-1.87K" R0402_RESC1005L 121.8,142.225 r270 bottom value=1.87K
R414 "1536-Res-0402-1.87K" R0402_RESC1005L 124.34,142.225 r270 bottom value=1.87K
R417 "0000-Res-0402-DNP" R0402_RESC1005L 169.666,95.27 r180 top value=DNP
R418 "1572-Res-0402-10K" R0402_RESC1005L 174.928,6.923 r90 top value=10K
R419 "1572-Res-0402-10K" R0402_RESC1005L 238.5,161 r90 top value=10K
R420 "2254-Res-0402-5.6k" R0402_RESC1005L 237.35,163.4 r270 top value=5.6K
R421 "2254-Res-0402-5.6k" R0402_RESC1005L 232.6,163.4 r270 top value=5.6K
R422 "2254-Res-0402-5.6k" R0402_RESC1005L 233.7,163.4 r90 top value=5.6K
R423 "2254-Res-0402-5.6k" R0402_RESC1005L 236.25,163.4 r90 top value=5.6K
R426 "1536-Res-0402-1.87K" R0402_RESC1005L 126.88,142.225 r270 bottom value=1.87K
R427 "1536-Res-0402-1.87K" R0402_RESC1005L 129.42,142.225 r270 bottom value=1.87K
R430 "2233-Res-0402-4.7K" R0402_RESC1005L 29.705,69.488 r90 top value=4.7K
R431 "2233-Res-0402-4.7K" R0402_RESC1005L 18.465,144.605 r270 top value=4.7K
R432 "1572-Res-0402-10K" R0402_RESC1005L 181.5,176.781 r0 top value=10K
R433 "1552-Res-0402-120" R0402_RESC1005L 118.749,176.111 r90 top value=120
R434 "1977-Res-0402-100K" R0402_RESC1005L 117.795,176.111 r90 top value=100K
R435 "0195-Res-0603-0.0ohm" R/0603 121.3,174.15 r180 top value=0.0
R436 "0195-Res-0603-0.0ohm" R/0603 114.889,177.944 r270 top value=0.0
R437 "0195-Res-0603-0.0ohm" R/0603 116.495,177.962 r270 top value=0.0
R438 "0195-Res-0603-0.0ohm" R/0603 217.175,183.967 r180 top value=0.0
R439 "0000-Res-0603-DNP" R/0603 222.4,179.092 r0 top value=DNP
R440 "1539-Res-0402-86.6k" R0402_RESC1005L 214.375,180.318 r270 top value=86.6K
R441 "1539-Res-0402-86.6k" R0402_RESC1005L 215.375,180.318 r270 top value=86.6K
R442 "1536-Res-0402-1.87K" R0402_RESC1005L 235.1,115.85 r90 top value=1.87K
R443 "1536-Res-0402-1.87K" R0402_RESC1005L 234.1,115.85 r90 top value=1.87K
R444 "1539-Res-0402-86.6k" R0402_RESC1005L 236.5,121.425 r270 top value=86.6K
R445 "2233-Res-0402-4.7K" R0402_RESC1005L 234.653,121.425 r270 top value=4.7K
R446 "2233-Res-0402-4.7K" R0402_RESC1005L 235.578,121.425 r270 top value=4.7K
R447 "0195-Res-0603-0.0ohm" R/0603 5,11 r90 top value=0.0
R448 "0195-Res-0603-0.0ohm" R/0603 4.125,190.85 r180 top value=0.0
R449 "0195-Res-0603-0.0ohm" R/0603 245.85,190.9 r0 top value=0.0
R450 "0000-Res-0402-DNP" R0402_RESC1005L 72.095,174.337 r180 top value=DNP
R451 "0000-Res-0402-DNP" R0402_RESC1005L 74.67,174.337 r180 top value=DNP
R452 "1550-Res-0402-15K" R0402_RESC1005L 144.69,181.81 r0 top value=15K
R453 "1572-Res-0402-10K" R0402_RESC1005L 171.726,150.205 r90 top value=10K
R454 "1572-Res-0402-10K" R0402_RESC1005L 172.782,150.205 r90 top value=10K
R455 "1572-Res-0402-10K" R0402_RESC1005L 172.95,158.05 r270 top value=10K
R456 "1572-Res-0402-10K" R0402_RESC1005L 171.95,158.05 r270 top value=10K
R457 "1572-Res-0402-10K" R0402_RESC1005L 73.883,56.393 r0 top value=10K
R458 "1542-Res-0402-1M" R0402_RESC1005L 73.883,55.475 r0 top value=1M
R459 "1572-Res-0402-10K" R0402_RESC1005L 109.8,76 r90 bottom value=10K
R460 "1572-Res-0402-10K" R0402_RESC1005L 111.45,33.8 r0 bottom value=10K
R461 "0703-Res-0402-22ohm" R0402_RESC1005L 106.085,89.8 r90 top value=22
R462 "0703-Res-0402-22ohm" R0402_RESC1005L 107.135,89.8 r90 top value=22
R463 "0195-Res-0603-0.0ohm" R/0603 81.05,55.25 r90 top value=0.0
R464 "0195-Res-0603-0.0ohm" R/0603 79.325,55.25 r90 top value=0.0
R465 "2233-Res-0402-4.7K" R0402_RESC1005L 27.145,79.45 r180 top value=4.7K
R467 "1542-Res-0402-1M" R0402_RESC1005L 85.025,26.5 r180 top value=1M
R468 "1536-Res-0402-1.87K" R0402_RESC1005L 216.8,136.36 r270 top value=1.87K
R469 "1536-Res-0402-1.87K" R0402_RESC1005L 215.75,136.36 r270 top value=1.87K
R470 "1572-Res-0402-10K" R0402_RESC1005L 221.984,140.656 r0 top value=10K
R471 "1536-Res-0402-1.87K" R0402_RESC1005L 221.984,141.606 r0 top value=1.87K
R472 "1536-Res-0402-1.87K" R0402_RESC1005L 221.984,142.603 r0 top value=1.87K
R473 "1572-Res-0402-10K" R0402_RESC1005L 221.984,138.731 r0 top value=10K
R474 "1572-Res-0402-10K" R0402_RESC1005L 221.984,137.781 r0 top value=10K
R475 "0000-Res-0402-DNP" R0402_RESC1005L 221.984,139.681 r0 top value=DNP
R476 "1572-Res-0402-10K" R0402_RESC1005L 214.672,136.36 r270 top value=10K
R477 "1536-Res-0402-1.87K" R0402_RESC1005L 130.618,34.978 r0 top value=1.87K
R478 "1536-Res-0402-1.87K" R0402_RESC1005L 132.736,34.978 r180 top value=1.87K
RA1 "1265-ResArr-22ohm" EXB34V 108.5,88.8 r90 bottom value="2 x 22"
RA3 "1407-ResArr-1206-10K" RESNET-1206-4 36.725,146.075 r270 top value="4 x 10K"
RA4 "0000-ResArr-0606-DNP" EXB34V 103.332,154.459 r180 top value=DNP
RA5 "0000-ResArr-0606-DNP" EXB34V 214.35,99.925 r90 top value=DNP
RA6 "0000-ResArr-0606-DNP" EXB34V 216.85,99.925 r90 top value=DNP
RA7 "1848-ResArr-0804-22ohm" RES_4_X_0804 157.85,73.55 r270 top value=4x22
RA8 "1407-ResArr-1206-10K" RESNET-1206-4 235.912,130.325 r0 top value="4 x 10K"
RA9 "1407-ResArr-1206-10K" RESNET-1206-4 235.75,140.225 r0 top value="4 x 10K"
RA10 "1407-ResArr-1206-10K" RESNET-1206-4 213.975,117.725 r90 top value="4 x 10K"
RA11 "1848-ResArr-0804-22ohm" RES_4_X_0804 116.884,88.85 r90 bottom value=4x22
RA14 "1848-ResArr-0804-22ohm" RES_4_X_0804 126.575,73.472 r270 bottom value=4x22
RA15 "1265-ResArr-22ohm" EXB34V 151.174,73.55 r270 top value="2 x 22"
RA16 "1848-ResArr-0804-22ohm" RES_4_X_0804 123.746,73.472 r270 bottom value=4x22
RA17 "1265-ResArr-22ohm" EXB34V 117.876,73.47 r270 bottom value="2 x 22"
RA18 "1848-ResArr-0804-22ohm" RES_4_X_0804 135.681,107.6 r90 bottom value=4x22
RA19 "1848-ResArr-0804-22ohm" RES_4_X_0804 105.8,88.85 r90 bottom value=4x22
RA20 "1848-ResArr-0804-22ohm" RES_4_X_0804 129.4,73.472 r270 bottom value=4x22
RA21 "1848-ResArr-0804-22ohm" RES_4_X_0804 120.86,73.47 r270 bottom value=4x22
RA22 "1848-ResArr-0804-22ohm" RES_4_X_0804 143.4,107.6 r90 bottom value=4x22
RA23 "1848-ResArr-0804-22ohm" RES_4_X_0804 111.65,88.85 r90 bottom value=4x22
RA24 "1848-ResArr-0804-22ohm" RES_4_X_0804 155.425,73.578 r270 bottom value=4x22
RA25 "1848-ResArr-0804-22ohm" RES_4_X_0804 114.225,88.85 r90 bottom value=4x22
RA26 "1848-ResArr-0804-22ohm" RES_4_X_0804 163.035,73.528 r270 top value=4x22
RA27 "1848-ResArr-0804-22ohm" RES_4_X_0804 160.453,73.528 r270 top value=4x22
RA28 "1848-ResArr-0804-22ohm" RES_4_X_0804 148.6,73.55 r270 top value=4x22
RA29 "1265-ResArr-22ohm" EXB34V 150.925,73.55 r270 bottom value="2 x 22"
RA30 "1848-ResArr-0804-22ohm" RES_4_X_0804 97.125,88.85 r90 bottom value=4x22
RA31 "1848-ResArr-0804-22ohm" RES_4_X_0804 145.983,73.55 r270 top value=4x22
RA32 "1848-ResArr-0804-22ohm" RES_4_X_0804 132.075,73.55 r270 top value=4x22
RA33 "1848-ResArr-0804-22ohm" RES_4_X_0804 153.497,73.548 r270 top value=4x22
RA34 "1848-ResArr-0804-22ohm" RES_4_X_0804 140.475,73.55 r270 bottom value=4x22
RA35 "1265-ResArr-22ohm" EXB34V 133.047,70.269 r270 bottom value="2 x 22"
RA36 "1848-ResArr-0804-22ohm" RES_4_X_0804 142.8,73.55 r270 bottom value=4x22
RA37 "1265-ResArr-22ohm" EXB34V 242.45,179.928 r270 top value="2 x 22"
RA38 "1848-ResArr-0804-22ohm" RES_4_X_0804 138.24,107.6 r90 bottom value=4x22
RA39 "1848-ResArr-0804-22ohm" RES_4_X_0804 143.375,73.55 r270 top value=4x22
RA40 "1848-ResArr-0804-22ohm" RES_4_X_0804 140.83,107.6 r90 bottom value=4x22
RA41 "1265-ResArr-22ohm" EXB34V 246.01,174.875 r180 top value="2 x 22"
RA45 "1848-ResArr-0804-22ohm" RES_4_X_0804 148.6,73.55 r90 bottom value=4x22
S1 "SLW-913535-2A-SMT" SWITCH_SLW-913535-2A-SMT 243.425,40.665 r180 top
S2 "SLW-913535-2A-SMT" SWITCH_SLW-913535-2A-SMT 234.675,40.665 r180 top
S3 "SLW-913535-2A-SMT" SWITCH_SLW-913535-2A-SMT 243.425,53.215 r180 top
S4 "SLW-913535-2A-SMT" SWITCH_SLW-913535-2A-SMT 234.675,53.215 r180 top
U1 "MCP1799-5002H/DB" SOT223 34.6,125.775 r0 top
U2 "LTC4368IDD-2#PBF" "10-DFN (3X3)_ADI" 5.477,157.886 r90 top
U3 "PCA9306DCT" TSSO3X5-G8/X.35 35.1,82.3 r90 top
U4 "INA226A" MSOP-10 21.925,92.075 r180 top
U5 "TPS62823DLCR" DLC0008A 6.575,81.522 r90 top
U6 "AOZ2261AQI-15" QFN4X4-22L_EP2_S_AOS 18.62,104.738 r180 top
U7 "TPS61089RNRR" "11-VQFN-HR (2.5X2)" 13.859,68.542 r90 top
U8 "LTC2954CTS8-2#TRMPBF" TSOT-23-8_ADI 20.15,82.45 r180 top
U9 "PCA9306DCT" TSSO3X5-G8/X.35 143.13,161.8 r270 top
U10 "PCA9306DCT" TSSO3X5-G8/X.35 150.75,161.8 r270 top
U11 "PCA9306DCT" TSSO3X5-G8/X.35 158.37,161.8 r270 top
U12 "TPD4E001" SOT23-6 43.725,186.78 r0 top
U13 "AP2127K" SOT23-5AN 47.291,184.588 r270 top
U14 "93LC56BT-I/OT" SOT23-6 49.1,175.566 r270 top
U15 "FT4232H" LQFP64_N 53.1,163.7 r0 top
U16 "AP22653AW6-7" SOT23-6 111.2,28.625 r0 bottom
U17 "TPD4E001" SOT23-6 116.525,27.575 r0 bottom
U18 "TPD4E001" SOT23-6 105.05,27.575 r0 bottom
U19 "PCA9306DCT" TSSO3X5-G8/X.35 75.65,132.305 r0 top
U20 "D3V3F4U10LP-7" 10-UFDFN 136.635,188.7 r270 top
U21 "AP22615AWU-7" TSOT26 140.37,178.736 r270 top
U22 "PTN5110NHQZ" QFN40P260X260X40-17N-D 153.396,175.715 r0 top
U23 "D3V3F4U10LP-7" 10-UFDFN 133.75,188.7 r270 top
U24 "D3V3F4U10LP-7" 10-UFDFN 130.15,188.7 r270 top
U25 "PESD15VL2BT,215" SOT23_N 172.15,31.975 r90 top
U26 "AP2132BMP-2.5TRG1" "SOP-9 TP_ALT" 90.191,154.081 r90 top
U27 "USB5744T-I/2G" "56-VQFN (7X7)" 99.594,163.293 r270 top
U28 "AP22653AW6-7" SOT23-6 120.899,160.89 r90 top
U29 "AP22653AW6-7" SOT23-6 120.899,168.413 r90 top
U30 "D3V3F4U10LP-7" 10-UFDFN 103.725,180.45 r90 top
U31 "D3V3F4U10LP-7" 10-UFDFN 101.525,192.908 r270 bottom
U32 "D3V3F4U10LP-7" 10-UFDFN 99.53,180.467 r270 top
U33 "D3V3F4U10LP-7" 10-UFDFN 69.4,180.792 r270 top
U34 "D3V3F4U10LP-7" 10-UFDFN 66.3,180.795 r270 top
U35 "AP2132BMP-2.5TRG1" "SOP-9 TP_ALT" 74.49,165.004 r90 top
U36 "AP2132BMP-2.5TRG1" "SOP-9 TP_ALT" 80.295,160.667 r90 top
U37 "DP83867ISRGZ" RGZ0048B 83.05,176 r270 bottom locked
U38 "D3V3F4U10LP-7" 10-UFDFN 80.2,182.55 r270 bottom
U39 "D3V3F4U10LP-7" 10-UFDFN 85.4,182.583 r270 bottom
U40 "PESD15VL2BT,215" SOT23_N 175.725,20.75 r270 top
U41 "TMUXHS4212IRKSR" "VQFN-20 (4.5X2.5)" 144.673,52.4 r90 top
U42 "TPD4E001" SOT23-6 140.891,10.418 r180 bottom
U43 "D5V0M5B6LP16-7" U-DFN1616-6 234.35,185.875 r0 top
U44 "74AVC4T774PW-Q100J" TSSOP16_NXP 218.325,118.475 r90 top
U45 "74LVC1G14SE-7" SOT353-5N 184.4,177.25 r90 top
U46 "D3V3F4U10LP-7" 10-UFDFN 204.5,182.767 r90 top
U47 "D3V3F4U10LP-7" 10-UFDFN 211.5,182.767 r90 top
U48 "TCAN1044VDRQ1" SOIC-8 34.65,21.5 r180 top
U49 "TCAN1044VDRQ1" SOIC-8 23.651,19.008 r180 top
U50 "ESDCAN06-2BWY" SOT-323 13.501,7.708 r0 top
U51 "ESDCAN06-2BWY" SOT-323 32.95,7.625 r0 top
U52 "WM8904CGEFL/RV" QFN40P400X400X75_HS-33N 239.471,174.275 r90 top locked
U53 "D3V3F4U10LP-7" 10-UFDFN 207.5,182.767 r90 top
U54 "TMP1075DSGR" WSON-8(2.1X2.1)_PAD 77.62,141.713 r90 top
U55 "M24C02-FDW6TP" TSSOP8 78.375,39.375 r90 top
U56 "MX25U25645GXDI00" T-PBGA-24 215.75,94.35 r180 top
U57 "PCA9306DCT" TSSO3X5-G8/X.35 135.327,39.835 r0 top
U58 "AMC6821SDBQR" 16-SSOP_DBQ_TI 159.937,42.3 r180 top
U59 "TMUX1574DYYR" SOP50P326X110-16N 98.725,51.55 r0 top
U60 "74AVC4T774PW-Q100J" TSSOP16_NXP 172.45,154.13 r180 top
U61 "74AVC4T774PW-Q100J" TSSOP16_NXP 97.389,60.064 r90 top
U62 "74AVC4T774PW-Q100J" TSSOP16_NXP 236.5,126.05 r0 top
U63 "74AUP1G08GW,125" SOT353-5N 164.1,59.198 r270 bottom
U64 "74AVC4T774PW-Q100J" TSSOP16_NXP 236.5,135.875 r0 top
U65 "UCC12040DVER" SOIC-16 31.503,56.09 r90 top
U66 "UCC12040DVER" SOIC-16 31.498,37.675 r90 top
U67 "ISO6721RBDR" SOIC-8 30.443,47.7 r180 top
U68 "ISO6721RBDR" SOIC-8 30.436,29.283 r180 top
U69 "TCAN1044VDRQ1" SOIC-8 22.45,29.283 r180 top
U70 "TCAN1044VDRQ1" SOIC-8 22.45,47.7 r180 top
U71 "ESDCAN06-2BWY" SOT-323 7.55,48.917 r270 top
U72 "ESDCAN06-2BWY" SOT-323 7.55,30.5 r270 top
U73 "LM25145RGYR" "VQFN-20 (3.5X4.5)" 20.742,123.675 r180 top
U74 "LM2901" PW014_N 34.15,164.7 r90 top
U75 "CYPD3177-24LQXQ" IC-CYPRESS-CYPD3177-24LQXQ 28.725,182.4 r90 top
U76 "SN65HVD01DRCR" "10-VSON (3X3)" 178.6,178.231 r90 top
U77 "TRS3122ERGER" QFN4X4-24_EP 162.9,182.2 r270 top
U78 "MMICT390200012" TDK_MMICT5818-00-012 228.585,181.975 r180 bottom
U79 "MMICT390200012" TDK_MMICT5818-00-012 228.585,170.858 r180 bottom
U80 "AP22653AW6-7" SOT23-6 218.25,179.817 r90 top
U81 "PCA9306DCT" TSSO3X5-G8/X.35 226.89,104.99 r270 top
U82 "74AVC4T774PW-Q100J" TSSOP16_NXP 230.13,95.275 r0 top
U83 "PCA9306DCT" TSSO3X5-G8/X.35 235.875,118.575 r270 top
U84 "D3V3F4U10LP-7" 10-UFDFN 139.6,188.7 r270 top
U85 "TCA9543APWR" TSSOP14 216.071,140.475 r180 top
U86 "AP2127K-1.8TRG1" SOT23-5AN 40.05,177.859 r0 top
U87 "74AVC4T774PW-Q100J" TSSOP16 44.54,139.036 r90 top
U88 "PCA9306DCT" TSSO3X5-G8/X.35 227.174,83.065 r270 top
U89 "74AVC4T774PW-Q100J" TSSOP16_NXP 230.129,75.623 r0 top
U95 "TUSB321AIRWBR" "12-X2QFN (1.6X1.6)" 111.916,174.461 r180 top
U96 "TMUXHS4212IRKSR" "VQFN-20 (4.5X2.5)" 108.86,176.025 r0 bottom
U97 "AP22615AWU-7" TSOT26 125.158,181.398 r180 top
U98 "D3V3F4U10LP-7" 10-UFDFN 117.15,188.7 r270 top
U99 "D3V3F4U10LP-7" 10-UFDFN 123.535,188.7 r270 top
U100 "D3V3F4U10LP-7" 10-UFDFN 120.675,188.7 r270 top
U104 "MCP1799-5002H/DB" SOT223 30.025,153.375 r90 top
X1 "000-TestPoint" TESTPOINT_1 38.663,122.675 r0 top
X2 "5011" TESTPOINT_4 36.625,67.375 r180 top
X3 "000-TestPoint" TESTPOINT_1 11.794,147.972 r0 top
X4 "5011" TESTPOINT_4 106.924,147.497 r180 top
X5 "5011" TESTPOINT_4 174.95,170 r180 top
X6 "5011" TESTPOINT_4 178.575,72.978 r0 top
X7 "5011" TESTPOINT_4 215.582,132.62 r270 top
X8 "5011" TESTPOINT_4 2.4,150.6 r180 top
X9 "5011" TESTPOINT_4 178,38.7 r180 top locked
X10 "000-TestPoint" TESTPOINT_1 16.8,89.391 r180 top
X11 "000-TestPoint" TESTPOINT_1 41.725,75.975 r270 top
X12 "000-TestPoint" TESTPOINT_1 16.802,93.325 r180 top
X13 "000-TestPoint" TESTPOINT_1 3.625,80.85 r90 top
X14 "000-TestPoint" TESTPOINT_1 27.025,77.7 r180 top
X15 "000-TestPoint" TESTPOINT_1 18.225,72.525 r180 top
X16 "000-TestPoint" TESTPOINT_1 221.6,182.717 r0 top
X17 "000-TestPoint2" TESTPOINT_3 21.391,99.225 r180 top
X18 "000-TestPoint" TESTPOINT_1 9.005,91.275 r90 top
X19 "000-TestPoint" TESTPOINT_1 6.941,91.273 r90 top
X20 "000-TestPoint2" TESTPOINT_3 15.403,60.674 r90 top
X21 "000-TestPoint" TESTPOINT_1 31.532,69.988 r0 top
X22 "000-TestPoint" TESTPOINT_1 25.709,85.25 r180 top
X23 "000-TestPoint" TESTPOINT_1 1.327,103.076 r0 top
X24 "000-TestPoint" TESTPOINT_1 1.3,105.116 r0 top
X25 "000-TestPoint" TESTPOINT_1 217,176.767 r0 top
X27 "000-TestPoint2" TESTPOINT_3 169.9,59.2 r180 top
X28 "000-TestPoint" TESTPOINT_1 15.275,85.487 r180 top
X29 "000-TestPoint" TESTPOINT_1 41.99,175.099 r180 top
X30 "000-TestPoint" TESTPOINT_1 38.275,167.799 r270 top
X31 "000-TestPoint" TESTPOINT_1 96.467,27.133 r90 top
X32 "000-TestPoint" TESTPOINT_1 94.3,27.131 r0 top
X33 "000-TestPoint" TESTPOINT_1 154.355,170.447 r90 top
X34 "000-TestPoint" TESTPOINT_1 141.44,171.69 r270 top
X36 "000-TestPoint2" TESTPOINT_3 148.88,179.35 r0 top
X37 "000-TestPoint2" TESTPOINT_3 149.396,181.19 r0 top
X38 "000-TestPoint2" TESTPOINT_3 156.746,179.215 r90 top
X39 "000-TestPoint2" TESTPOINT_3 158.646,179.215 r90 top
X41 "000-TestPoint" TESTPOINT_1 142.02,186.337 r270 top
X42 "000-TestPoint" TESTPOINT_1 104.532,159.411 r180 top
X43 "000-TestPoint" TESTPOINT_1 87.33,149.549 r90 top
X45 "000-TestPoint" TESTPOINT_1 92.236,159.282 r180 top
X46 "000-TestPoint" TESTPOINT_1 100.907,156.762 r180 top
X47 "000-TestPoint" TESTPOINT_1 97.996,154.511 r0 top
X48 "000-TestPoint2" TESTPOINT_3 122.484,163.226 r90 top
X49 "000-TestPoint2" TESTPOINT_3 122.511,170.736 r0 top
X50 "000-TestPoint" TESTPOINT_1 127.444,161.872 r270 top
X51 "000-TestPoint" TESTPOINT_1 127.536,169.363 r0 top
X52 "000-TestPoint" TESTPOINT_1 111.375,157.412 r90 top
X53 "000-TestPoint" TESTPOINT_1 111.4,165 r0 top
X54 "000-TestPoint" TESTPOINT_1 72.385,160.248 r90 top
X55 "000-TestPoint" TESTPOINT_1 78.11,155.9 r180 top
X56 "000-TestPoint" TESTPOINT_1 76.588,169.798 r90 top
X57 "000-TestPoint" TESTPOINT_1 82.405,165.457 r270 top
X59 "000-TestPoint2" TESTPOINT_3 89.5,173.523 r270 bottom
X60 "000-TestPoint2" TESTPOINT_3 169.875,57.008 r180 top
X61 "000-TestPoint2" TESTPOINT_3 213.35,129.025 r90 top
X62 "000-TestPoint2" TESTPOINT_3 170.2,6.175 r0 top
X63 "000-TestPoint" TESTPOINT_1 155.226,9.122 r180 top
X64 "000-TestPoint2" TESTPOINT_3 176.225,6.128 r270 top
X65 "000-TestPoint" TESTPOINT_1 169.9,55.025 r0 top
X66 "000-TestPoint2" TESTPOINT_3 173.021,88.837 r270 top
X67 "000-TestPoint2" TESTPOINT_3 169.921,96.9 r0 top
X68 "000-TestPoint" TESTPOINT_1 166.844,110.052 r90 top
X69 "000-TestPoint2" TESTPOINT_3 168.694,88.837 r270 top
X70 "000-TestPoint" TESTPOINT_1 166.85,101.321 r270 top
X71 "000-TestPoint" TESTPOINT_1 244.5,176.85 r180 top
X72 "000-TestPoint" TESTPOINT_1 246.2,172.575 r180 top
X73 "000-TestPoint" TESTPOINT_1 81.5,11.676 r0 top
X74 "000-TestPoint" TESTPOINT_1 211.453,91.575 r180 top
X75 "000-TestPoint" TESTPOINT_1 234.55,168.85 r180 top
X76 "000-TestPoint" TESTPOINT_1 211.453,93.85 r180 top
X80 "000-TestPoint" TESTPOINT_1 170.175,27.218 r0 top
X82 "000-TestPoint" TESTPOINT_1 19.457,51.392 r270 top
X83 "000-TestPoint" TESTPOINT_1 19.457,32.975 r270 top
X84 "000-TestPoint" TESTPOINT_1 23.5,38.575 r270 top
X85 "000-TestPoint" TESTPOINT_1 23.507,56.992 r0 top
X86 "000-TestPoint" TESTPOINT_1 24.707,99.271 r270 top
X87 "000-TestPoint2" TESTPOINT_3 21.392,130.891 r270 top
X89 "000-TestPoint2" TESTPOINT_3 31.225,129.675 r180 top
X90 "000-TestPoint" TESTPOINT_1 19.76,134.6 r270 top
X91 "000-TestPoint2" TESTPOINT_3 30.325,187.25 r270 top
X92 "000-TestPoint2" TESTPOINT_3 25.425,187.08 r0 top
X93 "000-TestPoint" TESTPOINT_1 24.35,169.4 r270 top
X94 "000-TestPoint" TESTPOINT_1 25.045,142.015 r90 top
X95 "000-TestPoint" TESTPOINT_1 29.025,169.775 r270 top
X96 "000-TestPoint" TESTPOINT_1 20.675,150.475 r90 top
X98 "000-TestPoint2" TESTPOINT_3 109.099,180.765 r270 top
X99 "000-TestPoint2" TESTPOINT_3 110.19,179.512 r270 top
X100 "000-TestPoint2" TESTPOINT_3 111.106,178.123 r0 top
X101 "000-TestPoint2" TESTPOINT_3 118.737,174.371 r90 top
X102 "000-TestPoint" TESTPOINT_1 115.239,182.432 r0 top
X103 "000-TestPoint2" TESTPOINT_3 120.484,175.718 r270 top
X104 "000-TestPoint" TESTPOINT_1 107.71,179.622 r0 top
X105 "000-TestPoint2" TESTPOINT_3 116.495,180.566 r270 top
X106 "000-TestPoint2" TESTPOINT_3 114.889,180.566 r0 top
X107 "000-TestPoint" TESTPOINT_1 125.825,191.662 r0 top
X108 "000-TestPoint" TESTPOINT_1 4.123,161.3 r180 top
X109 "000-TestPoint" TESTPOINT_1 6.293,161.3 r180 top
X110 "000-TestPoint" TESTPOINT_1 35.6,157.875 r90 top
X111 "000-TestPoint" TESTPOINT_1 169.875,52.035 r180 top
X112 "000-TestPoint" TESTPOINT_1 109.101,171.4 r0 top
X113 "000-TestPoint" TESTPOINT_1 25.975,158.45 r270 top
X114 "000-TestPoint" TESTPOINT_1 32.225,169.625 r0 top
X115 "000-TestPoint" TESTPOINT_1 234.55,179.25 r270 top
